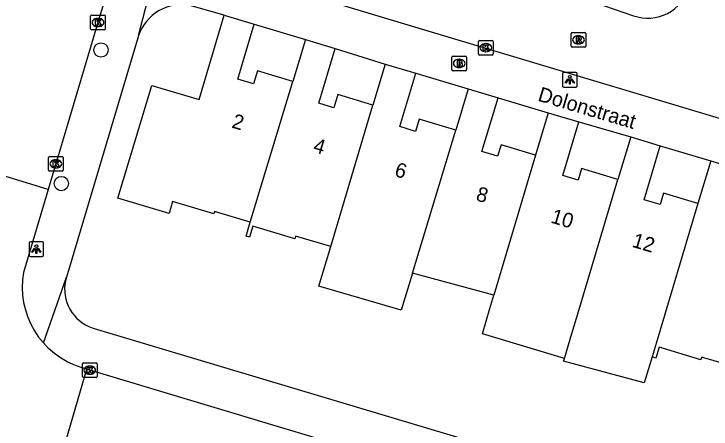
# Model space of a CAD drawing. Extents: x 162186 to 163152, y 385513 to 386513.
# Drawn here: x 162576.37 to 162623.88, y 386132.31 to 386160.61 of the extents above; entities that cross this region are included whole.
import ezdxf

# ---------------------------------------------------------------- set-up
doc = ezdxf.new("R2010")
doc.units = 0
for name, color, linetype in [('IMGEO_Boom', 7, 'Continuous'), ('IMGEO_Brandkraan', 7, 'Continuous'), ('IMGEO_Kolk', 7, 'Continuous'), ('IMGEO_Lichtpunt', 7, 'Continuous'), ('IMGEO_Openbare_ruimte_label', 7, 'Continuous'), ('IMGEO_Pand', 7, 'Continuous'), ('IMGEO_Pand_nummerreeks', 7, 'Continuous'), ('IMGEO_Rijbaan_lokaal_gesloten', 7, 'Continuous'), ('IMGEO_Rijbaan_lokaal_open', 7, 'Continuous'), ('IMGEO_Rioolput', 7, 'Continuous'), ('IMGEO_Voetpad_open', 7, 'Continuous')]:
    doc.layers.add(name, color=color, linetype=linetype)

msp = doc.modelspace()

# ---------------------------------------------------------------- linework, layer by layer
at = {"layer": 'IMGEO_Boom'}
for centre in [(162582.299, 386158.154), (162579.594, 386149.047)]:
    msp.add_circle(centre, 0.489, dxfattribs=at)
at = {"layer": 'IMGEO_Brandkraan'}
for p, q in [((162606.222, 386156.812), (162606.222, 386157.664)), ((162606.297, 386157.738), (162607.149, 386157.738)), ((162606.71, 386157.518), (162606.735, 386157.518)), ((162607.223, 386157.664), (162607.223, 386156.812)), ((162606.733, 386156.958), (162606.708, 386156.958)), ((162607.149, 386156.738), (162606.297, 386156.738))]:
    msp.add_line(p, q, dxfattribs=at)
for points in [[(162606.222, 386156.812), (162606.222, 386157.664)], [(162606.297, 386157.738), (162607.149, 386157.738)], [(162606.57, 386157.438), (162606.57, 386157.038), (162606.783, 386157.038)], [(162606.801, 386157.438), (162606.57, 386157.438)], [(162606.749, 386157.357), (162606.695, 386157.357), (162606.695, 386157.281)], [(162606.695, 386157.281), (162606.748, 386157.281)], [(162607.223, 386157.664), (162607.223, 386156.812)], [(162606.757, 386157.205), (162606.695, 386157.205), (162606.695, 386157.124)], [(162606.695, 386157.124), (162606.757, 386157.124)], [(162607.149, 386156.738), (162606.297, 386156.738)]]:
    msp.add_lwpolyline(points, dxfattribs=at)
for centre, radius, start, end in [((162606.299, 386157.662), 0.0765, 91.552, 178.448), ((162606.299, 386157.662), 0.0765, 91.552, 178.448), ((162606.75, 386157.319), 0.0379, 267.8285, 90.9355), ((162606.805, 386157.293), 0.145, 59.4692, 91.5367), ((162606.83, 386157.34), 0.0922, 285.5137, 58.1501), ((162607.147, 386157.662), 0.0765, 1.552, 88.448), ((162607.147, 386157.662), 0.0765, 1.552, 88.448), ((162606.299, 386156.814), 0.0765, 181.552, 268.448), ((162606.299, 386156.814), 0.0765, 181.552, 268.448), ((162606.758, 386157.164), 0.0404, 269.8759, 90.5077), ((162606.789, 386157.289), 0.251, 268.6676, 293.5347), ((162606.835, 386157.148), 0.105, 301.3115, 78.989), ((162607.147, 386156.814), 0.0765, 271.552, 358.448), ((162607.147, 386156.814), 0.0765, 271.552, 358.448)]:
    msp.add_arc(centre, radius, start, end, dxfattribs=at)
for centre, major_axis, ratio, start_param, end_param in [((162606.709, 386157.238), (-0.387, 0.002), 0.722429, 4.712389, 7.853982), ((162606.734, 386157.238), (-0.39, 0.002), 0.717154, 1.570796, 4.712389)]:
    msp.add_ellipse(centre, major_axis=major_axis, ratio=ratio, start_param=start_param, end_param=end_param, dxfattribs=at)
at = {"layer": 'IMGEO_Kolk'}
for p, q in [((162581.595, 386159.599), (162581.595, 386160.451)), ((162581.67, 386160.525), (162582.522, 386160.525)), ((162582.083, 386160.305), (162582.108, 386160.305)), ((162582.596, 386160.451), (162582.596, 386159.599)), ((162582.106, 386159.745), (162582.081, 386159.745)), ((162582.522, 386159.525), (162581.67, 386159.525)), ((162608.032, 386157.882), (162608.032, 386158.734)), ((162608.107, 386158.808), (162608.959, 386158.808)), ((162609.033, 386158.734), (162609.033, 386157.882)), ((162608.52, 386158.588), (162608.545, 386158.588)), ((162608.959, 386157.808), (162608.107, 386157.808)), ((162608.543, 386158.028), (162608.518, 386158.028)), ((162578.721, 386149.962), (162578.721, 386150.814)), ((162578.796, 386150.888), (162579.648, 386150.888)), ((162579.209, 386150.668), (162579.234, 386150.668)), ((162579.722, 386150.814), (162579.722, 386149.962)), ((162579.648, 386149.888), (162578.796, 386149.888)), ((162579.232, 386150.108), (162579.207, 386150.108)), ((162581.034, 386135.897), (162581.034, 386136.749)), ((162581.109, 386136.823), (162581.961, 386136.823)), ((162581.522, 386136.603), (162581.547, 386136.603)), ((162582.035, 386136.749), (162582.035, 386135.897)), ((162581.545, 386136.043), (162581.52, 386136.043)), ((162581.961, 386135.823), (162581.109, 386135.823))]:
    msp.add_line(p, q, dxfattribs=at)
for points in [[(162581.595, 386159.599), (162581.595, 386160.451)], [(162581.67, 386160.525), (162582.522, 386160.525)], [(162581.916, 386160.225), (162582.039, 386160.225), (162582.039, 386160.074), (162582.169, 386160.225), (162582.333, 386160.225), (162582.187, 386160.074), (162582.34, 386159.825), (162582.188, 386159.825), (162582.103, 386159.989), (162582.039, 386159.922), (162582.039, 386159.825), (162581.916, 386159.825), (162581.916, 386160.225)], [(162582.596, 386160.451), (162582.596, 386159.599)], [(162582.522, 386159.525), (162581.67, 386159.525)], [(162608.032, 386157.882), (162608.032, 386158.734)], [(162608.107, 386158.808), (162608.959, 386158.808)], [(162609.033, 386158.734), (162609.033, 386157.882)], [(162608.353, 386158.508), (162608.476, 386158.508), (162608.476, 386158.357), (162608.606, 386158.508), (162608.77, 386158.508), (162608.624, 386158.357), (162608.777, 386158.108), (162608.625, 386158.108), (162608.54, 386158.272), (162608.476, 386158.205), (162608.476, 386158.108), (162608.353, 386158.108), (162608.353, 386158.508)], [(162608.959, 386157.808), (162608.107, 386157.808)], [(162578.721, 386149.962), (162578.721, 386150.814)], [(162578.796, 386150.888), (162579.648, 386150.888)], [(162579.722, 386150.814), (162579.722, 386149.962)], [(162579.042, 386150.588), (162579.165, 386150.588), (162579.165, 386150.437), (162579.295, 386150.588), (162579.459, 386150.588), (162579.313, 386150.437), (162579.466, 386150.188), (162579.314, 386150.188), (162579.229, 386150.352), (162579.165, 386150.285), (162579.165, 386150.188), (162579.042, 386150.188), (162579.042, 386150.588)], [(162579.648, 386149.888), (162578.796, 386149.888)], [(162581.034, 386135.897), (162581.034, 386136.749)], [(162581.109, 386136.823), (162581.961, 386136.823)], [(162581.355, 386136.523), (162581.478, 386136.523), (162581.478, 386136.372), (162581.608, 386136.523), (162581.772, 386136.523), (162581.626, 386136.372), (162581.779, 386136.123), (162581.627, 386136.123), (162581.542, 386136.287), (162581.478, 386136.22), (162581.478, 386136.123), (162581.355, 386136.123), (162581.355, 386136.523)], [(162582.035, 386136.749), (162582.035, 386135.897)], [(162581.961, 386135.823), (162581.109, 386135.823)]]:
    msp.add_lwpolyline(points, dxfattribs=at)
for centre, start, end in [((162581.672, 386160.449), 91.552, 178.448), ((162581.672, 386160.449), 91.552, 178.448), ((162582.52, 386160.449), 1.552, 88.448), ((162582.52, 386160.449), 1.552, 88.448), ((162581.672, 386159.601), 181.552, 268.448), ((162581.672, 386159.601), 181.552, 268.448), ((162582.52, 386159.601), 271.552, 358.448), ((162582.52, 386159.601), 271.552, 358.448), ((162608.109, 386158.732), 91.552, 178.448), ((162608.109, 386158.732), 91.552, 178.448), ((162608.957, 386158.732), 1.552, 88.448), ((162608.957, 386158.732), 1.552, 88.448), ((162608.109, 386157.884), 181.552, 268.448), ((162608.109, 386157.884), 181.552, 268.448), ((162608.957, 386157.884), 271.552, 358.448), ((162608.957, 386157.884), 271.552, 358.448), ((162578.798, 386150.812), 91.552, 178.448), ((162578.798, 386150.812), 91.552, 178.448), ((162579.646, 386150.812), 1.552, 88.448), ((162579.646, 386150.812), 1.552, 88.448), ((162578.798, 386149.964), 181.552, 268.448), ((162578.798, 386149.964), 181.552, 268.448), ((162579.646, 386149.964), 271.552, 358.448), ((162579.646, 386149.964), 271.552, 358.448), ((162581.111, 386136.747), 91.552, 178.448), ((162581.111, 386136.747), 91.552, 178.448), ((162581.959, 386136.747), 1.552, 88.448), ((162581.959, 386136.747), 1.552, 88.448), ((162581.111, 386135.899), 181.552, 268.448), ((162581.111, 386135.899), 181.552, 268.448), ((162581.959, 386135.899), 271.552, 358.448), ((162581.959, 386135.899), 271.552, 358.448)]:
    msp.add_arc(centre, 0.0765, start, end, dxfattribs=at)
for centre, major_axis, ratio, start_param, end_param in [((162582.082, 386160.025), (-0.387, 0.002), 0.722429, 4.712389, 7.853982), ((162582.107, 386160.025), (-0.39, 0.002), 0.717154, 1.570796, 4.712389), ((162608.519, 386158.308), (-0.387, 0.002), 0.722429, 4.712389, 7.853982), ((162608.544, 386158.308), (-0.39, 0.002), 0.717154, 1.570796, 4.712389), ((162579.208, 386150.388), (-0.387, 0.002), 0.722429, 4.712389, 7.853982), ((162579.233, 386150.388), (-0.39, 0.002), 0.717154, 1.570796, 4.712389), ((162581.521, 386136.323), (-0.387, 0.002), 0.722429, 4.712389, 7.853982), ((162581.546, 386136.323), (-0.39, 0.002), 0.717154, 1.570796, 4.712389)]:
    msp.add_ellipse(centre, major_axis=major_axis, ratio=ratio, start_param=start_param, end_param=end_param, dxfattribs=at)
at = {"layer": 'IMGEO_Lichtpunt'}
for p, q in [((162613.757, 386156.517), (162613.757, 386155.71)), ((162613.757, 386156.517), (162613.757, 386155.71)), ((162614.659, 386156.612), (162613.851, 386156.612)), ((162614.659, 386156.612), (162613.851, 386156.612)), ((162614.753, 386155.71), (162614.753, 386156.517)), ((162614.753, 386155.71), (162614.753, 386156.517)), ((162613.851, 386155.616), (162614.659, 386155.616)), ((162613.851, 386155.616), (162614.659, 386155.616)), ((162577.394, 386144.976), (162577.394, 386144.169)), ((162577.394, 386144.976), (162577.394, 386144.169)), ((162578.296, 386145.071), (162577.488, 386145.071)), ((162578.296, 386145.071), (162577.488, 386145.071)), ((162578.39, 386144.169), (162578.39, 386144.976)), ((162578.39, 386144.169), (162578.39, 386144.976)), ((162577.488, 386144.075), (162578.296, 386144.075)), ((162577.488, 386144.075), (162578.296, 386144.075))]:
    msp.add_line(p, q, dxfattribs=at)
for points in [[(162614.131, 386156.181), (162614.17, 386156.153), (162613.982, 386155.891), (162613.944, 386155.918), (162614.131, 386156.181)], [(162614.233, 386156.133), (162614.28, 386156.133), (162614.28, 386155.811), (162614.233, 386155.811), (162614.233, 386156.133)], [(162614.343, 386156.153), (162614.381, 386156.18), (162614.568, 386155.918), (162614.529, 386155.89), (162614.343, 386156.153)], [(162577.768, 386144.64), (162577.807, 386144.612), (162577.619, 386144.35), (162577.581, 386144.377), (162577.768, 386144.64)], [(162577.87, 386144.592), (162577.917, 386144.592), (162577.917, 386144.27), (162577.87, 386144.27), (162577.87, 386144.592)], [(162577.98, 386144.612), (162578.018, 386144.639), (162578.205, 386144.377), (162578.166, 386144.349), (162577.98, 386144.612)]]:
    msp.add_lwpolyline(points, dxfattribs=at)
for centre in [(162614.256, 386156.315), (162577.893, 386144.774)]:
    msp.add_circle(centre, 0.0994, dxfattribs=at)
for centre, start, end in [((162613.851, 386156.517), 90, 180), ((162613.851, 386156.517), 90, 180), ((162614.659, 386156.517), 0, 90), ((162614.659, 386156.517), 0, 90), ((162613.851, 386155.71), 180, 270), ((162613.851, 386155.71), 180, 270), ((162614.659, 386155.71), 270, 0), ((162614.659, 386155.71), 270, 360), ((162577.488, 386144.976), 90, 180), ((162577.488, 386144.976), 90, 180), ((162578.296, 386144.976), 0, 90), ((162578.296, 386144.976), 0, 90), ((162577.488, 386144.169), 180, 270), ((162577.488, 386144.169), 180, 270), ((162578.296, 386144.169), 270, 0), ((162578.296, 386144.169), 270, 360)]:
    msp.add_arc(centre, 0.0946, start, end, dxfattribs=at)
at = {"layer": 'IMGEO_Pand'}
for points in [[(162592.476, 386146.417), (162590.04, 386147.146), (162589.989, 386146.977), (162587.185, 386147.816), (162586.941, 386146.999), (162583.455, 386148.042), (162585.757, 386155.735), (162588.987, 386154.769), (162590.707, 386160.519)], [(162590.707, 386160.519), (162592.748, 386159.908)], [(162595.385, 386156.011), (162592.958, 386156.737), (162592.689, 386155.838), (162591.625, 386156.156), (162592.748, 386159.908)], [(162596.249, 386158.862), (162595.385, 386156.011)], [(162596.249, 386158.862), (162598.271, 386158.257)], [(162600.838, 386154.399), (162598.449, 386155.114), (162598.178, 386154.208), (162597.151, 386154.515), (162598.271, 386158.257)], [(162601.673, 386157.192), (162600.838, 386154.399)], [(162601.673, 386157.192), (162603.759, 386156.568)], [(162606.489, 386152.686), (162603.995, 386153.433), (162603.747, 386152.603), (162602.669, 386152.926), (162603.759, 386156.568)], [(162592.476, 386146.417), (162595.385, 386156.011)], [(162607.331, 386155.499), (162606.489, 386152.686)], [(162607.331, 386155.499), (162609.368, 386154.889)], [(162611.925, 386150.99), (162609.574, 386151.693), (162609.337, 386150.902), (162608.271, 386151.221), (162609.368, 386154.889)], [(162597.966, 386144.748), (162600.838, 386154.399)], [(162612.787, 386153.87), (162611.925, 386150.99)], [(162612.787, 386153.87), (162614.864, 386153.248)], [(162617.538, 386149.325), (162615.062, 386150.066), (162614.826, 386149.276), (162613.77, 386149.592), (162614.864, 386153.248)], [(162603.523, 386142.93), (162606.489, 386152.686)], [(162618.406, 386152.225), (162617.538, 386149.325)], [(162618.406, 386152.225), (162620.424, 386151.621)], [(162622.99, 386147.683), (162620.649, 386148.383), (162620.418, 386147.61), (162619.322, 386147.938), (162620.424, 386151.621)], [(162611.925, 386150.99), (162609.072, 386141.447)], [(162623.859, 386150.584), (162622.99, 386147.683)], [(162623.859, 386150.584), (162625.885, 386149.978)], [(162613.885, 386137.109), (162614.401, 386138.833), (162614.869, 386140.397), (162617.538, 386149.325)], [(162622.99, 386147.683), (162620.132, 386138.136), (162619.86, 386137.229)], [(162597.966, 386144.748), (162595.566, 386145.467), (162595.511, 386145.284), (162592.655, 386146.139), (162592.428, 386145.38), (162592.187, 386145.452), (162592.476, 386146.417)], [(162603.523, 386142.93), (162602.758, 386140.414), (162597.158, 386142.048), (162597.674, 386143.772), (162597.966, 386144.748)], [(162609.072, 386141.447), (162603.777, 386142.862), (162603.523, 386142.93)], [(162613.885, 386137.109), (162608.303, 386138.805), (162608.799, 386140.534), (162609.072, 386141.447)], [(162625.656, 386136.495), (162623.244, 386137.217), (162623.189, 386137.035), (162620.351, 386137.884), (162620.131, 386137.148), (162619.86, 386137.229)], [(162619.86, 386137.229), (162619.333, 386135.467), (162613.834, 386136.938), (162613.885, 386137.109)]]:
    msp.add_lwpolyline(points, dxfattribs=at)
at = {"layer": 'IMGEO_Rijbaan_lokaal_gesloten'}
msp.add_lwpolyline([(162583.806, 386165.71), (162582.091, 386160.026), (162579.217, 386150.388), (162578.692, 386148.647)], dxfattribs=at)
at = {"layer": 'IMGEO_Rijbaan_lokaal_open'}
for points in [[(162632.571, 386151.052), (162591.943, 386163.26)], [(162615.964, 386161.394), (162618.598, 386160.486)], [(162578.692, 386148.647), (162571.134, 386150.964)], [(162578.692, 386148.647), (162577.014, 386142.992), (162576.948, 386142.479), (162576.929, 386141.962), (162576.955, 386141.446), (162577.028, 386140.934), (162577.146, 386140.43), (162577.308, 386139.939), (162577.514, 386139.464), (162577.761, 386139.01), (162578.048, 386138.58), (162578.373, 386138.177)], [(162581.327, 386136.385), (162580.938, 386136.496), (162580.453, 386136.676), (162579.987, 386136.899), (162579.542, 386137.163), (162579.122, 386137.466), (162578.732, 386137.805), (162578.373, 386138.177)], [(162579.302, 386129.465), (162581.327, 386136.385)], [(162677.459, 386107.446), (162651.748, 386115.1), (162602.19, 386130.13), (162581.53, 386136.322), (162581.327, 386136.385)]]:
    msp.add_lwpolyline(points, dxfattribs=at)
msp.add_arc((162619.567, 386163.294), 2.971, 250.9622, 343.2682, dxfattribs=at)
at = {"layer": 'IMGEO_Rioolput'}
for p, q in [((162614.349, 386158.414), (162614.349, 386159.266)), ((162614.424, 386159.34), (162615.276, 386159.34)), ((162615.35, 386159.266), (162615.35, 386158.414)), ((162614.837, 386159.12), (162614.862, 386159.12)), ((162615.276, 386158.34), (162614.424, 386158.34)), ((162614.86, 386158.56), (162614.835, 386158.56))]:
    msp.add_line(p, q, dxfattribs=at)
for points in [[(162614.349, 386158.414), (162614.349, 386159.266)], [(162614.424, 386159.34), (162615.276, 386159.34)], [(162615.35, 386159.266), (162615.35, 386158.414)], [(162614.938, 386159.038), (162614.686, 386159.04), (162614.686, 386158.64)], [(162614.686, 386158.64), (162614.81, 386158.64), (162614.81, 386158.802), (162614.821, 386158.802)], [(162614.864, 386158.959), (162614.81, 386158.959), (162614.81, 386158.878)], [(162614.81, 386158.878), (162614.862, 386158.878)], [(162614.868, 386158.773), (162614.939, 386158.64), (162615.079, 386158.64), (162615.014, 386158.766)], [(162615.276, 386158.34), (162614.424, 386158.34)]]:
    msp.add_lwpolyline(points, dxfattribs=at)
for centre, radius, start, end in [((162614.426, 386159.264), 0.0765, 91.552, 178.448), ((162614.426, 386159.264), 0.0765, 91.552, 178.448), ((162615.274, 386159.264), 0.0765, 1.552, 88.448), ((162615.274, 386159.264), 0.0765, 1.552, 88.448), ((162614.82, 386158.749), 0.0533, 26.0293, 88.6989), ((162614.846, 386159.067), 0.19, 274.7715, 282.9687), ((162614.87, 386158.863), 0.0964, 77.0061, 93.1865), ((162614.884, 386158.92), 0.0378, 276.6634, 79.6772), ((162614.937, 386158.928), 0.109, 350.3612, 89.416), ((162614.935, 386158.928), 0.112, 277.5842, 350.9817), ((162614.919, 386158.713), 0.108, 29.5134, 73.7905), ((162614.426, 386158.416), 0.0765, 181.552, 268.448), ((162614.426, 386158.416), 0.0765, 181.552, 268.448), ((162615.274, 386158.416), 0.0765, 271.552, 358.448), ((162615.274, 386158.416), 0.0765, 271.552, 358.448)]:
    msp.add_arc(centre, radius, start, end, dxfattribs=at)
for centre, major_axis, ratio, start_param, end_param in [((162614.836, 386158.84), (-0.387, 0.002), 0.722429, 4.712389, 7.853982), ((162614.861, 386158.84), (-0.39, 0.002), 0.717154, 1.570796, 4.712389)]:
    msp.add_ellipse(centre, major_axis=major_axis, ratio=ratio, start_param=start_param, end_param=end_param, dxfattribs=at)
at = {"layer": 'IMGEO_Voetpad_open'}
for points in [[(162584.866, 386159.147), (162586.348, 386164.94)], [(162590.707, 386160.519), (162588.616, 386161.113), (162588.349, 386161.176), (162588.077, 386161.216), (162587.803, 386161.23), (162587.528, 386161.221), (162587.255, 386161.186), (162586.987, 386161.128), (162586.725, 386161.046), (162586.471, 386160.94), (162586.228, 386160.813), (162585.997, 386160.664), (162585.78, 386160.495), (162585.58, 386160.308), (162585.396, 386160.103), (162585.232, 386159.883), (162585.088, 386159.649), (162584.966, 386159.403), (162584.866, 386159.147)], [(162592.748, 386159.908), (162596.249, 386158.862)], [(162584.866, 386159.147), (162584.832, 386159.041), (162579.939, 386142.667)], [(162598.271, 386158.257), (162601.673, 386157.192)], [(162603.759, 386156.568), (162607.331, 386155.499)], [(162609.368, 386154.889), (162612.787, 386153.87)], [(162614.864, 386153.248), (162618.406, 386152.225)], [(162620.424, 386151.621), (162623.859, 386150.584)], [(162578.373, 386138.177), (162579.939, 386142.667)], [(162579.939, 386142.667), (162579.878, 386142.423), (162579.839, 386142.174), (162579.822, 386141.923), (162579.828, 386141.672), (162579.856, 386141.422), (162579.906, 386141.175), (162579.979, 386140.934), (162580.072, 386140.701), (162580.186, 386140.476), (162580.32, 386140.263), (162580.472, 386140.063), (162580.641, 386139.876), (162580.826, 386139.706), (162581.026, 386139.553), (162581.239, 386139.419), (162581.463, 386139.304), (162581.696, 386139.209), (162581.825, 386139.167), (162651.073, 386118.462), (162651.275, 386118.412)]]:
    msp.add_lwpolyline(points, dxfattribs=at)

# ---------------------------------------------------------------- texts
at = {"layer": 'IMGEO_Openbare_ruimte_label'}
msp.add_text('Dolonstraat', height=1, rotation=343.5038, dxfattribs=at).set_placement((162612.02, 386154.701))
at = {"layer": 'IMGEO_Pand_nummerreeks'}
for s, rotation, p in [('2', 343.4104, (162591.154, 386152.874)), ('4', 343.4104, (162596.702, 386151.22)), ('6', 343.4129, (162602.249, 386149.568)), ('8', 343.4129, (162607.799, 386147.915)), ('10', 343.4129, (162612.902, 386146.395)), ('12', 343.4129, (162618.442, 386144.745))]:
    msp.add_text(s, height=1, rotation=rotation, dxfattribs=at).set_placement(p)

doc.saveas('drawing.dxf')
